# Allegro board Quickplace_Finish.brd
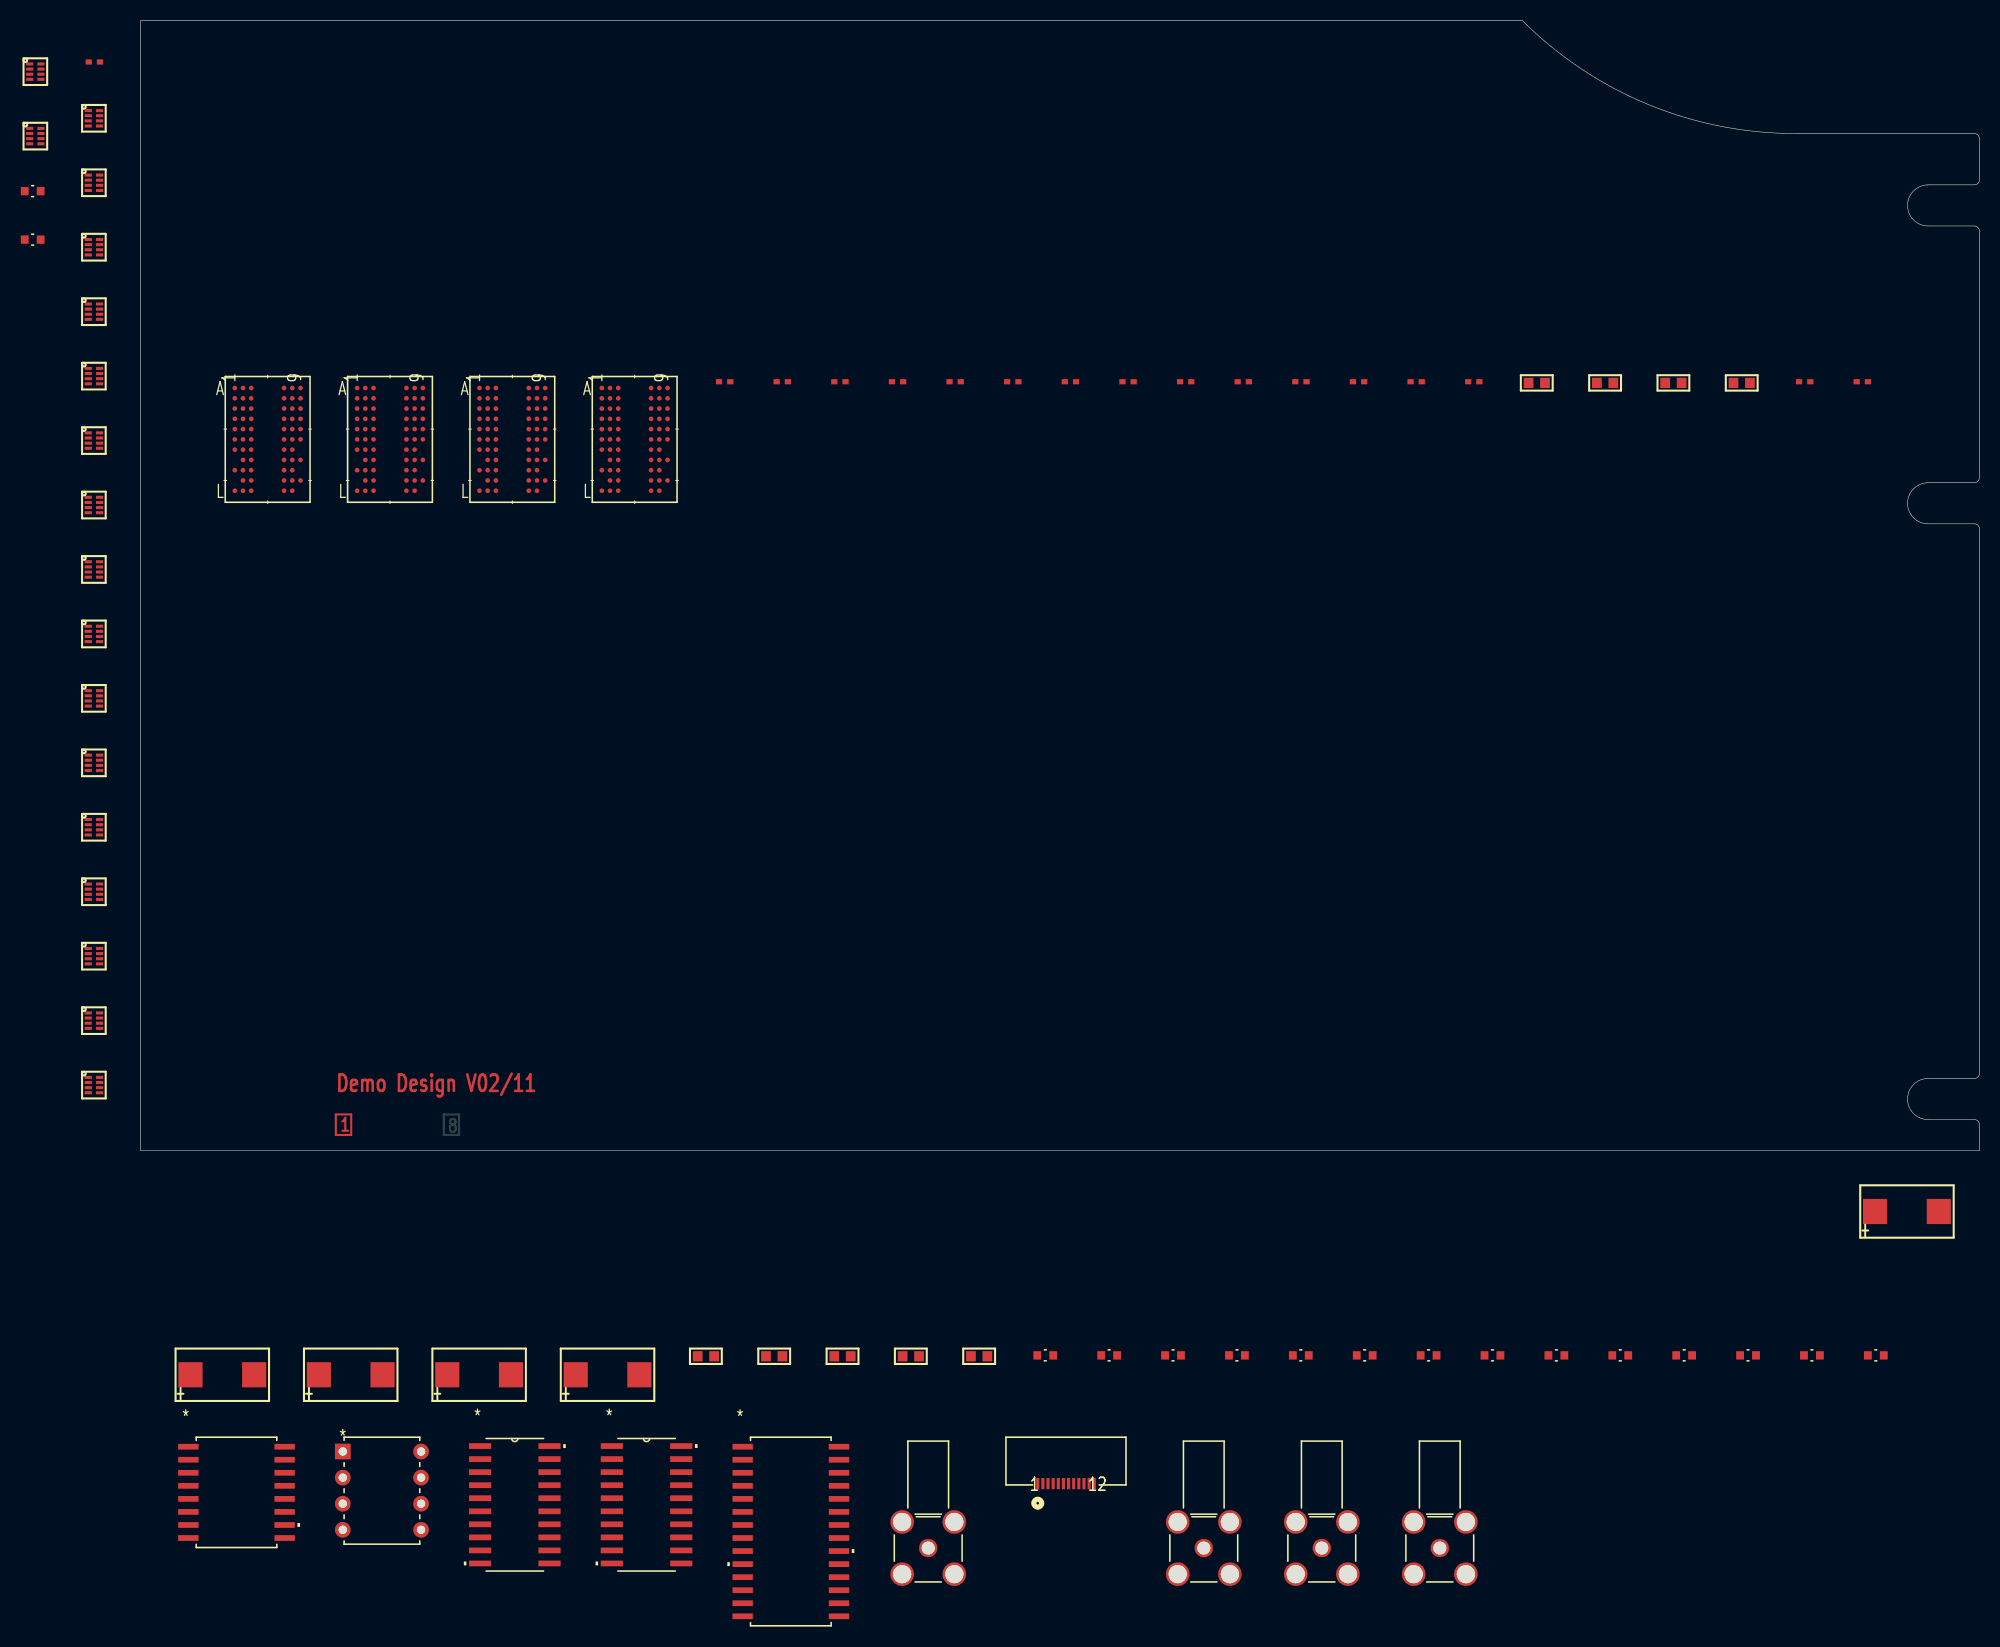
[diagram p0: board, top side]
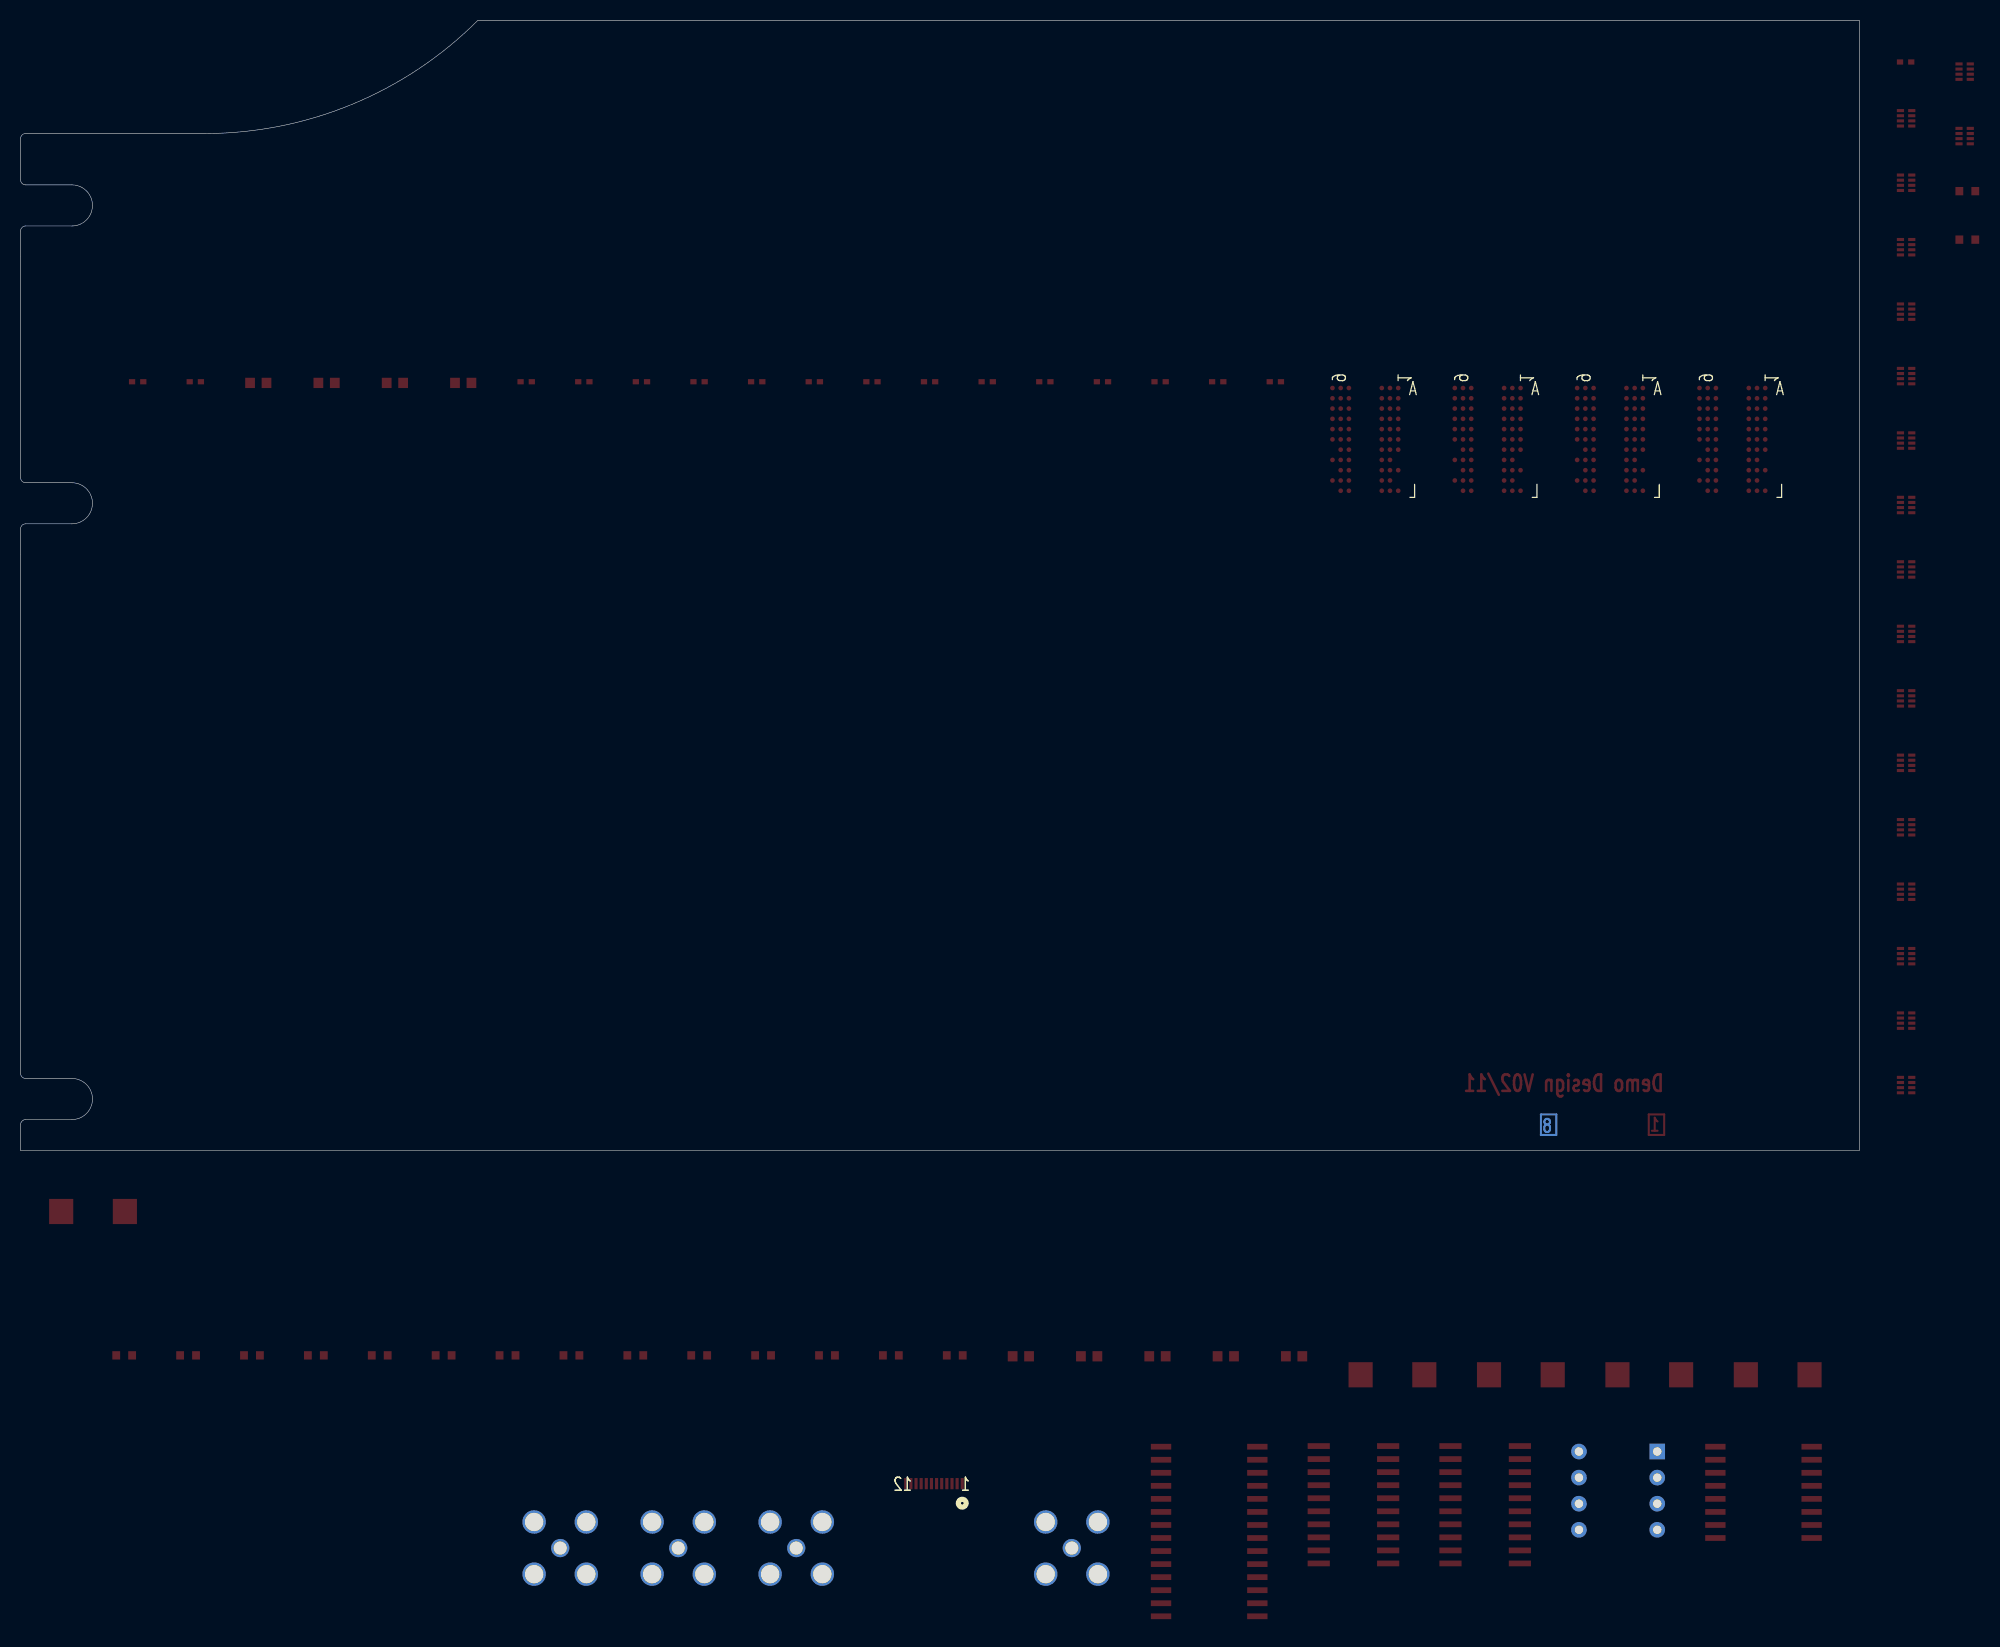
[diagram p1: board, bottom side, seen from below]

Outline 179 x 110 mm; copper layers: TOP, GND1, I1, POW1, GND2, I2, POW2, BOTTOM. Coordinates in mm from the lower left corner of the outline.
Outline path: 0,110 134.5,110 arc(146.68,101.86) 161.06,99 178.5,99 arc(178.85,98.85) 179,98.5 179,94.5 arc(178.85,94.15) 178.5,94 174,94 arc(172.59,93.41) 172,92 arc(172.59,90.59) 174,90 178.5,90 arc(178.85,89.85) 179,89.5 179,65.5 arc(178.85,65.15) 178.5,65 174,65 arc(172.59,64.41) 172,63 arc(172.59,61.59) 174,61 178.5,61 arc(178.85,60.85) 179,60.5 179,7.5 arc(178.85,7.15) 178.5,7 174,7 arc(172.59,6.41) 172,5 arc(172.59,3.59) 174,3 178.5,3 arc(178.85,2.85) 179,2.5 179,0 0,0 0,110

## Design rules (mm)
constraint set DEFAULT: min track width 0.12
net group 220V: nets 220VIN N9903369
net group D+: nets D+ N64620
net group D-: nets D- N64584
net group DDR2_DQS0: nets DDR2_M.MDQS0 DDR2_M.MDQS#0
net group DDR2_DQS1: nets DDR2.DQS1 DDR2.DQS#1
net group DDR2_DQS2: nets DDR2_M.MDQS2 DDR2_M.MDQS#2
net group DDR2_DQS3: nets DDR2.DQS3 DDR2.DQS#3
net group DDR3.DQ1: nets DDR3.DQ1 DDR3_M.MDQ1
net group DDR3.DQ2: nets DDR3.DQ2 DDR3_M.MDQ2
net group DDR3.DQS0: nets DDR3.DQS0 DDR3_M.MDQS0
net group DDR3.DQS#0: nets DDR3.DQS#0 DDR3_M.MDQS#0
net group DP_DDR2.DQS#0: nets DDR2.DQS0 DDR2.DQS#0
net group DP_DDR2.DQS#2: nets DDR2.DQS2 DDR2.DQS#2
net group L: nets N9927430 N9927434
net group LVDS_CLKN1: nets LVDS_CLKN1 N11185
net group LVDS_CLKP1: nets LVDS_CLKP1 N09783
net group N04579: nets N04579 N05028
net group N06416: nets N06416 N06432
net group N07590: nets N07590 N07606
net group N08030: nets N08030 N08046
net group N14938: nets N04399 N14938
net group N14942: nets N04484 N14942
net group N15446: nets N04241 N15446
net group N15450: nets N04318 N15450
net group PCIE.PERN0: nets N56952 PCIE.PERN0
net group PCIE.PERN1: nets N56956 PCIE.PERN1
net group PCIE.PERN2: nets N56950 PCIE.PERN2
net group PCIE.PERN3: nets N56954 PCIE.PERN3
net group PCIE.PERP0: nets N57097 PCIE.PERP0
net group PCIE.PERP1: nets N57240 PCIE.PERP1
net group PCIE.PERP2: nets N57385 PCIE.PERP2
net group PCIE.PERP3: nets N57532 PCIE.PERP3
net group PCIE.PETN0: nets N58134 PCIE.PETN0
net group PCIE.PETN1: nets N58138 PCIE.PETN1
net group PCIE.PETN2: nets N58142 PCIE.PETN2
net group PCIE.PETN3: nets N58146 PCIE.PETN3
net group PCIE.PETP0: nets N58154 PCIE.PETP0
net group PCIE.PETP1: nets N58162 PCIE.PETP1
net group PCIE.PETP2: nets N58150 PCIE.PETP2
net group PCIE.PETP3: nets N58158 PCIE.PETP3
net group PCIE.REFCLK+: nets N06722 PCIE.REFCLK+
net group PCIE.REFCLK-: nets N06858 PCIE.REFCLK-
net group STDA_SSRX+: nets N64724 STDA_SSRX+
net group STDA_SSRX-: nets N64696 STDA_SSRX-
net group STDA_SSTX+: nets N64864 STDA_SSTX+
net group STDA_SSTX-: nets N64816 STDA_SSTX-
net group AD_DA: nets AD_CS AD_DB0 AD_DB1 AD_DB2 AD_DB3 AD_DB4 AD_DB5 AD_DB6 AD_DB7 AD_DB8 AD_DB9 AD_DB10 AD_DB11 AD_DB12 AD_DB13 AD_FL0 AD_FL1 AD_IRQ2 AD_RD N00752 N00770 N00798 N00829 N00863 N00900 N01007 N01138 N01306 N01356 N01440 N01527 N01617 N01710 N04350 N06404 N07578 N08018
net group DDR2.A0: nets DDR2.A0
net group DDR2.A1: nets DDR2.A1
net group DDR2.A2: nets DDR2.A2
net group DDR2.A3: nets DDR2.A3
net group DDR2.A4: nets DDR2.A4
net group DDR2.A5: nets DDR2.A5
net group DDR2.A6: nets DDR2.A6
net group DDR2.A7: nets DDR2.A7
net group DDR2.A8: nets DDR2.A8
net group DDR2.A9: nets DDR2.A9
net group DDR2.A10: nets DDR2.A10
net group DDR2.A11: nets DDR2.A11
net group DDR2.A12: nets DDR2.A12
net group DDR2.A13: nets DDR2.A13
net group DDR2.BA0: nets DDR2.BA0
net group DDR2.BA1: nets DDR2.BA1
net group DDR2.CAS: nets DDR2.CAS
net group DDR2.ODT0: nets DDR2.ODT0
net group DDR2.RAS: nets DDR2.RAS
net group DDR2.S0: nets DDR2.S0
net group DDR2.WE: nets DDR2.WE
net group DDR2[0..71]: nets DDR2.CK1 DDR2.CK#1 DDR2_M.MDQS1 DDR2_M.MDQS3
net group DDR2_A_EL: nets DDR2_M.MA0 DDR2_M.MA1 DDR2_M.MA2 DDR2_M.MA3 DDR2_M.MA4 DDR2_M.MA5 DDR2_M.MA6 DDR2_M.MA7 DDR2_M.MA8 DDR2_M.MA9 DDR2_M.MA10 DDR2_M.MA11 DDR2_M.MA12 DDR2_M.MA13 DDR2_M.MBA0 DDR2_M.MBA1 DDR2_M.MCAS DDR2_M.MODT0 DDR2_M.MRAS DDR2_M.MS0 DDR2_M.MWE
net group DDR2_D0_EL: nets DDR2.DM0 DDR2.DQ0 DDR2.DQ1 DDR2.DQ2 DDR2.DQ3 DDR2.DQ4 DDR2.DQ5 DDR2.DQ6 DDR2.DQ7 DDR2.RDQS#0 DDR2_M.MDM0 DDR2_M.MDQ0 DDR2_M.MDQ1 DDR2_M.MDQ2 DDR2_M.MDQ3 DDR2_M.MDQ4 DDR2_M.MDQ5 DDR2_M.MDQ6 DDR2_M.MDQ7 DDR2_M.MRDQS#0
net group DDR2_D1_EL: nets DDR2.DM1 DDR2.DQ8 DDR2.DQ9 DDR2.DQ10 DDR2.DQ11 DDR2.DQ12 DDR2.DQ13 DDR2.DQ14 DDR2.DQ15 DDR2.RDQS#1 DDR2_M.MDM1 DDR2_M.MDQ8 DDR2_M.MDQ9 DDR2_M.MDQ10 DDR2_M.MDQ11 DDR2_M.MDQ12 DDR2_M.MDQ13 DDR2_M.MDQ14 DDR2_M.MDQ15 DDR2_M.MDQS#1 DDR2_M.MRDQS#1
net group DDR2_D2_EL: nets DDR2.DM2 DDR2.DQ16 DDR2.DQ17 DDR2.DQ18 DDR2.DQ19 DDR2.DQ20 DDR2.DQ21 DDR2.DQ22 DDR2.DQ23 DDR2.RDQS#2 DDR2_M.MDM2 DDR2_M.MDQ16 DDR2_M.MDQ17 DDR2_M.MDQ18 DDR2_M.MDQ19 DDR2_M.MDQ20 DDR2_M.MDQ21 DDR2_M.MDQ22 DDR2_M.MDQ23 DDR2_M.MRDQS#2
net group DDR2_D3_EL: nets DDR2.DM3 DDR2.DQ24 DDR2.DQ25 DDR2.DQ26 DDR2.DQ27 DDR2.DQ28 DDR2.DQ29 DDR2.DQ30 DDR2.DQ31 DDR2.RDQS#3 DDR2_M.MDM3 DDR2_M.MDQ24 DDR2_M.MDQ25 DDR2_M.MDQ26 DDR2_M.MDQ27 DDR2_M.MDQ28 DDR2_M.MDQ29 DDR2_M.MDQ30 DDR2_M.MDQ31 DDR2_M.MDQS#3 DDR2_M.MRDQS#3
net group DDR2_M.MCKE0: nets DDR2.CKE0
net group DDR3.DQ0: nets DDR3.DQ0
net group DDR3.DQ3: nets DDR3.DQ3
net group DDR3.DQ4: nets DDR3.DQ4
net group DDR3.DQ5: nets DDR3.DQ5
net group DDR3.DQ6: nets DDR3.DQ6
net group DDR3.DQ7: nets DDR3.DQ7
net group DDR3.DQ8: nets DDR3.DQ8
net group DDR3.DQ9: nets DDR3.DQ9
net group DDR3.DQ10: nets DDR3.DQ10
net group DDR3.DQ11: nets DDR3.DQ11
net group DDR3.DQ12: nets DDR3.DQ12
net group DDR3.DQ13: nets DDR3.DQ13
net group DDR3.DQ14: nets DDR3.DQ14
net group DDR3.DQ15: nets DDR3.DQ15
net group DDR3.DQS1: nets DDR3.DQS1
net group DDR3.DQS2: nets DDR3.DQS2
net group DDR3.DQS3: nets DDR3.DQS3
net group DDR3.DQS#1: nets DDR3.DQS#1
net group DDR3.DQS#2: nets DDR3.DQS#2
net group DDR3.DQS#3: nets DDR3.DQS#3
net group DDR3[0..54]: nets DDR3.A0 DDR3.A1 DDR3.A2 DDR3.A3 DDR3.A4 DDR3.A5 DDR3.A6 DDR3.A7 DDR3.A8 DDR3.A9 DDR3.A10 DDR3.A11 DDR3.A12 DDR3.A13 DDR3.A14 DDR3.BA0 DDR3.BA1 DDR3.BA2 DDR3.CAS DDR3.CK1 DDR3.CK#1 DDR3.CKE0 DDR3.ODT0 DDR3.RAS DDR3.RESET DDR3.S0 DDR3.WE
net group DDR3_M.MDM0: nets DDR3.DM0
net group DDR3_M.MDM1: nets DDR3.DM1
net group DDR3_M.MDM2: nets DDR3.DM2
net group DDR3_M.MDM3: nets DDR3.DM3
net group DDR3_SINGLE: nets N6521820 N6522732 N6522947 N6523197 N6859922
net group LOGIC: nets N01473 N01729 PGOOD_1.5V PGOOD_1.8V
net group MISC: nets 0.9VREF 0.75VREF 0VIN 1.2V 3.3V FB GATE N00305 N01108 N01139 N01192 N01323 N01619 N03618 N03634 N20586 N20602 N20606 N20610 N20650 N20774 N633172 N633472 N633476 N633480 N633520 N633648 N9903199 N9903225 N9903279 N9903519 N9908752 PE SENSE SHIELD1 SHIELD2 SKIP VCC VINT
net group N: nets N9927466
net group PCI_SINGLE: nets TDIO
net group PCIE[0..23]: nets PCIE.PERST# PCIE.PRSNT#1 PCIE.PRSNT#2 PCIE.SMCLK PCIE.SMDAT PCIE.WAKE#
net group POWER: nets 0.75VTT 1.0V 1.5V 1.8V 2.5V 2.5VREF 5V 12V +15V -15V AGND DGND GND_IN N00359 N00418 N00468 N04407 N04552 N20590 N20594 N20598 N20626 N20798 N20810 N633192 N633212 N633232 N633496 N633672 N633684
net group POWER_IN: nets DRAIN
net group VID: nets VID_D0 VID_D1 VID_D2 VID_D3 VID_D4 VID_FST VID_QCLK VID_SCL

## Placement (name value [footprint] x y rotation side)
C100  10u  [CAPP_TAJ_D]  171.94 -5.95 0 top
C101  10u  [CAPP_TAJ_D]  7.95 -21.85 0 top
C102  100n  [CAP_0603]  55.02 -20.05 0 top
C103  100n  [CAP_0603]  61.67 -20.05 0 top
C104  100n  [CAP_0603]  68.33 -20.05 0 top
C105  10u  [CAPP_TAJ_D]  20.45 -21.85 0 top
C106  100n  [CAP_0603]  74.97 -20.05 0 top
C107  10u  [CAPP_TAJ_D]  32.95 -21.85 0 top
C108  10u  [CAPP_TAJ_D]  45.45 -21.85 0 top
C109  100n  [CAP_0603]  81.62 -20.05 0 top
C504  100n  [CAP_0402]  167.6 74.84 0 top
C505  100n  [CAP_0402]  161.99 74.84 0 top
C506  2.2u  [CAP_0603]  135.91 74.72 0 top
C507  100n  [CAP_0402]  129.78 74.84 0 top
C508  100n  [CAP_0402]  56.85 74.84 0 top
C509  2.2u  [CAP_0603]  142.56 74.72 0 top
C510  100n  [CAP_0402]  62.46 74.84 0 top
C511  100n  [CAP_0402]  73.68 74.84 0 top
C512  2.2u  [CAP_0603]  149.21 74.72 0 top
C513  100n  [CAP_0402]  68.07 74.84 0 top
C514  100n  [CAP_0402]  84.9 74.84 0 top
C515  2.2u  [CAP_0603]  155.86 74.72 0 top
C516  100n  [CAP_0402]  79.29 74.84 0 top
C517  100n  [CAP_0402]  107.34 74.84 0 top
C518  100n  [CAP_0402]  90.51 74.84 0 top
C519  100n  [CAP_0402]  96.12 74.84 0 top
C520  100n  [CAP_0402]  101.73 74.84 0 top
C521  100n  [CAP_0402]  124.17 74.84 0 top
C522  100n  [CAP_0402]  112.95 74.84 0 top
C523  100n  [CAP_0402]  118.56 74.84 0 top
C524  22p  [CAP_0402]  -4.5 105.97 0 top
NOREF  -  []  0 0 0 top
NOREF#2  -  []  3.11 5.64 0 top
NOREF#3  -  []  0 0 0 top
NOREF#4  -  []  13 5 90 top
NOREF#5  -  []  0 0 0 top
NOREF#6  -  []  179 0 90 top
NOREF#7  -  []  0 0 90 top
NOREF#8  -  []  -50.46 -133.7 0 top
NOREF#9  -  []  213.2 115.2 0 top
NOREF#10  -  []  134.5 110 0 top
NOREF#11  -  []  15.87 7.79 0 top
NOREF#12  -  []  0 0 0 top
NOREF#13  -  []  178.5 99 90 top
NOREF#14  -  []  179 0 90 top
NOREF#15  -  []  179 0 90 top
NOREF#16  -  []  178.88 7.17 90 top
NOREF#17  -  []  172 5 90 top
NOREF#18  -  []  0 0 90 top
R100  1k  [RES_0603]  88.06 -19.96 0 top
R101  1k  [RES_0603]  94.28 -19.96 0 top
R102  1k  [RES_0603]  100.5 -19.96 0 top
R103  1k  [RES_0603]  106.72 -19.96 0 top
R104  1k  [RES_0603]  112.94 -19.96 0 top
R105  1k  [RES_0603]  119.16 -19.96 0 top
R106  1k  [RES_0603]  125.38 -19.96 0 top
R107  1k  [RES_0603]  131.6 -19.96 0 top
R108  9.1k  [RES_0603]  137.81 -19.96 0 top
R109  9.1k  [RES_0603]  144.03 -19.96 0 top
R110  9.1k  [RES_0603]  150.25 -19.96 0 top
R111  9.1k  [RES_0603]  156.47 -19.96 0 top
R112  1.2k  [RES_0603]  162.69 -19.96 0 top
R113  1.2k  [RES_0603]  168.91 -19.96 0 top
R500  22  [RES_RS4N]  -4.55 100.48 0 top
R501  22  [RES_RS4N]  -4.55 94.21 0 top
R502  22  [RES_RS4N]  -4.55 87.93 0 top
R503  22  [RES_RS4N]  -4.55 81.66 0 top
R504  7.5R  [RES_RS4N]  -4.55 25.18 0 top
R505  7.5R  [RES_RS4N]  -4.55 18.91 0 top
R506  200  [RES_0603]  -10.51 93.39 0 top
R507  7.5R  [RES_RS4N]  -4.55 12.63 0 top
R508  7.5R  [RES_RS4N]  -4.55 6.36 0 top
R509  7.5R  [RES_RS4N]  -10.25 105.03 0 top
R510  7.5R  [RES_RS4N]  -10.25 98.75 0 top
R511  200  [RES_0603]  -10.51 88.67 0 top
R512  22  [RES_RS4N]  -4.55 75.38 0 top
R513  22  [RES_RS4N]  -4.55 69.11 0 top
R514  22  [RES_RS4N]  -4.55 62.83 0 top
R515  22  [RES_RS4N]  -4.55 56.56 0 top
R516  22  [RES_RS4N]  -4.55 50.28 0 top
R517  22  [RES_RS4N]  -4.55 44.01 0 top
R518  22  [RES_RS4N]  -4.55 37.73 0 top
R519  22  [RES_RS4N]  -4.55 31.46 0 top
U100  AD713  [SO16_1_27X9_30]  9.33 -33.3 0 top
U101  AD780  [SO8_1_27X4_90]  19.68 -29.32 0 top
U102  74AHC245  [SO20_1_27X9_30]  36.43 -34.5 0 top
U103  74AHC245  [SO20_1_27X9_30]  49.25 -34.5 0 top
U104  AD7862  [SO28_1_27X9_30]  63.29 -37.11 0 top
U504  MT47H64M8CF-25EG  [FBGA60_8X10_MRN]  48.09 69.22 0 top
U505  MT47H64M8CF-25EG  [FBGA60_8X10_MRN]  24.27 69.22 0 top
U506  MT47H64M8CF-25EG  [FBGA60_8X10_MRN]  36.18 69.22 0 top
U507  MT47H64M8CF-25EG  [FBGA60_8X10_MRN]  12.36 69.22 0 top
X100  FPC12  [ZIF12_FLEX]  87.33 -32.45 0 top
X101  SMB  [SMB_90]  103.49 -38.72 0 top
X102  SMB  [SMB_90]  76.67 -38.72 0 top
X103  SMB  [SMB_90]  114.98 -38.72 0 top
X104  SMB  [SMB_90]  126.47 -38.72 0 top

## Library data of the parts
C100 C101 C105 C107 C108 = CAPPOL_T: User Part Number: FC-CAP-0049; alternate symbols: ((capp_taj_d_gd)); room: Analog_In; signal model: DEFAULT_CAPACITOR_1e+07pF_1_2
C102-C104 C106 C109 = CAP_V: User Part Number: FC-CAP-0037; alternate symbols: ((cap_0603_gd)); room: Analog_In; signal model: DEFAULT_CAPACITOR_100000pF_2_1
C504 C505 C507 C508 C510 C511 C513 C514 C516-C523 = CAP_V: User Part Number: FC-CAP-0099; Tolerance: TOL; signal model: DEFAULT_CAPACITOR_100000pF_2_1; room: DDR2
C506 C509 C512 C515 = CAP_V: User Part Number: FC-CAP-0100; alternate symbols: ((cap_0603_gd)); signal model: DEFAULT_CAPACITOR_2.2e+06pF_2_1; room: DDR2
C524 = CAP_H: User Part Number: FC-CAP-0080; Tolerance: TOL; signal model: DEFAULT_CAPACITOR_22pF_2_1; room: DDR2
R100-R107 = RES_V: User Part Number: FC-RES-0077; Tolerance: TOL; alternate symbols: ((res_0603_gd)); room: Analog_In; signal model: DEFAULT_RESISTOR_1000OHM_2_1
R108-R111 = RES_H: User Part Number: FC-RES-0100; Tolerance: TOL; alternate symbols: ((res_0603_gd)); room: Analog_In; signal model: DEFAULT_RESISTOR_9100OHM_2_1
R112 R113 = RES_V: User Part Number: FC-RES-0079; Tolerance: TOL; alternate symbols: ((res_0603_gd)); room: Analog_In; signal model: DEFAULT_RESISTOR_1200OHM_2_1
R500-R503 R512-R519 = RES_H_4x: User Part Number: FC-RAR-0225; alternate symbols: ((res_rs4n_gd)); signal model: rpack_x4_22r; room: DDR2
R504 R505 R507-R510 = RES_H_4x: User Part Number: FC-RAR-0282; alternate symbols: ((res_rs4n_gd)); signal model: rpack_x4_7.5R; room: DDR2
R506 R511 = RES_V: User Part Number: FC-RES-0060; Tolerance: TOL; alternate symbols: ((res_0603_gd)); signal model: DEFAULT_RESISTOR_200OHM_2_1; room: DDR2
U100 = AD713_SO: User Part Number: FC-IC-0023; Tolerance: TOL; room: Analog_In
U101 = IC_AD780_2: User Part Number: FC-IC-0024; Tolerance: TOL; room: Analog_In
U102 U103 = 74LS245: User Part Number: FC-IC-0927; Tolerance: TOL; room: Analog_In
U104 = IC_AD7862: User Part Number: FC-IC-0022; Tolerance: TOL; room: Analog_In
U504-U507 = MT47H64M8CF-25EG: User Part Number: PN; Tolerance: TOL
X100 = CON_12: User Part Number: FC-CON-0010; Tolerance: TOL
X101-X104 = CON_SMB: User Part Number: FC-CON-0002; Tolerance: TOL; alternate symbols: ((smb_90))

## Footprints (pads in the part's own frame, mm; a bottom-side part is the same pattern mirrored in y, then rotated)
CAP_0402
  rect 0.61x0.508 smd: 1(-0.546,0) 2(0.546,0)
CAP_0603
  rect 0.95x1 smd: 1(-0.8,0) 2(0.8,0)
CAPP_TAJ_D
  rect 2.35x2.45 smd: 1(-3.1,0) 2(3.1,0)
FBGA60_8X10_MRN
  round 0.457 smd: A1(-3.2,5) A2(-2.4,5) A3(-1.6,5) A7(1.6,5) A8(2.4,5) A9(3.2,5) B1(-3.2,4) B2(-2.4,4) B3(-1.6,4) B7(1.6,4) B8(2.4,4) B9(3.2,4) C1(-3.2,3) C2(-2.4,3) C3(-1.6,3) C7(1.6,3) C8(2.4,3) C9(3.2,3) D1(-3.2,2) D2(-2.4,2) D3(-1.6,2) D7(1.6,2) D8(2.4,2) D9(3.2,2) E1(-3.2,1) E2(-2.4,1) E3(-1.6,1) E7(1.6,1) E8(2.4,1) E9(3.2,1) F1(-3.2,0) F2(-2.4,0) F3(-1.6,0) F7(1.6,0) F8(2.4,0) F9(3.2,0) G1(-3.2,-1) G2(-2.4,-1) G3(-1.6,-1) G7(1.6,-1) G8(2.4,-1) H2(-2.4,-2) H3(-1.6,-2) H7(1.6,-2) H8(2.4,-2) H9(3.2,-2) J1(-3.2,-3) J2(-2.4,-3) J3(-1.6,-3) J7(1.6,-3) J8(2.4,-3) K2(-2.4,-4) K3(-1.6,-4) K7(1.6,-4) K8(2.4,-4) K9(3.2,-4) L1(-3.2,-5) L2(-2.4,-5) L3(-1.6,-5) L7(1.6,-5) L8(2.4,-5)
RES_0603
  rect 0.762x0.813 smd: 1(-0.775,0) 2(0.775,0)
RES_RS4N
  rect 0.7x0.3 smd: 1(-0.55,0.75) 2(-0.55,0.25) 3(-0.55,-0.25) 4(-0.55,-0.75) 5(0.55,-0.75) 6(0.55,-0.25) 7(0.55,0.25) 8(0.55,0.75)
SMB_90
  round 1.778 hole 1.27: 1(0,0)
  round 2.286 hole 1.778: 2(-2.54,2.54) 3(-2.54,-2.54) 4(2.54,-2.54) 5(2.54,2.54)
SO8_1_27X4_90
  rect 1.524x1.524 hole 0.813: 1(0,0)
  round 1.524 hole 0.813: 2(0,-2.54) 3(0,-5.08) 4(0,-7.62) 5(7.62,-7.62) 6(7.62,-5.08) 7(7.62,-2.54) 8(7.62,0)
SO16_1_27X9_30
  rect 1.981x0.559 smd: 1(-4.686,4.445) 2(-4.686,3.175) 3(-4.686,1.905) 4(-4.686,0.635) 5(-4.686,-0.635) 6(-4.686,-1.905) 7(-4.686,-3.175) 8(-4.686,-4.445) 9(4.686,-4.445) 10(4.686,-3.175) 11(4.686,-1.905) 12(4.686,-0.635) 13(4.686,0.635) 14(4.686,1.905) 15(4.686,3.175) 16(4.686,4.445)
SO20_1_27X9_30
  rect 2.159x0.559 smd: 1(-3.378,5.715) 2(-3.378,4.445) 3(-3.378,3.175) 4(-3.378,1.905) 5(-3.378,0.635) 6(-3.378,-0.635) 7(-3.378,-1.905) 8(-3.378,-3.175) 9(-3.378,-4.445) 10(-3.378,-5.715) 11(3.378,-5.715) 12(3.378,-4.445) 13(3.378,-3.175) 14(3.378,-1.905) 15(3.378,-0.635) 16(3.378,0.635) 17(3.378,1.905) 18(3.378,3.175) 19(3.378,4.445) 20(3.378,5.715)
SO28_1_27X9_30
  rect 1.981x0.559 smd: 1(-4.686,8.255) 2(-4.686,6.985) 3(-4.686,5.715) 4(-4.686,4.445) 5(-4.686,3.175) 6(-4.686,1.905) 7(-4.686,0.635) 8(-4.686,-0.635) 9(-4.686,-1.905) 10(-4.686,-3.175) 11(-4.686,-4.445) 12(-4.686,-5.715) 13(-4.686,-6.985) 14(-4.686,-8.255) 15(4.686,-8.255) 16(4.686,-6.985) 17(4.686,-5.715) 18(4.686,-4.445) 19(4.686,-3.175) 20(4.686,-1.905) 21(4.686,-0.635) 22(4.686,0.635) 23(4.686,1.905) 24(4.686,3.175) 25(4.686,4.445) 26(4.686,5.715) 27(4.686,6.985) 28(4.686,8.255)
ZIF12_FLEX
  rect 0.305x1.092 smd: 1(0,0) 2(0.5,0) 3(1,0) 4(1.5,0) 5(2,0) 6(2.5,0) 7(3,0) 8(3.5,0) 9(4,0) 10(4.5,0) 11(5,0) 12(5.5,0)

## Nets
1.8V: C504.2(B) C505.2(B) C506.2(B) C507.2(B) C508.2(B) C509.2(B) C510.2(B) C511.2(B) C512.2(B) C513.2(B) C514.2(B) C515.2(B) C516.2(B) C517.2(B) C518.2(B) C519.2(B) C520.2(B) C521.2(B) C522.2(B) C523.2(B)
2.5VREF: C107.1(P) U101.6(VOUT) U104.19(VREF)
3.3V: X100.2
5V: C104.2(B) C105.1(P) C106.2(B) C108.1(P) C109.2(B) R112.2(B) R113.2(B) U101.2 U102.1 U102.20(VCC) U103.1 U103.20(VCC) U104.24
+15V: C100.1(P) C102.2(B) U100.4
-15V: C101.2 C103.1 U100.13(V-)
AGND: C100.2 C101.1(P) C102.1 C103.2(B) C104.1 C107.2 C108.2 C109.1 R100.1 R101.1 R102.1 R103.1 R104.1 R105.1 R106.1 R107.1 U101.4 U104.16 U104.27 X101.2 X101.3 X101.4 X101.5(B3) X102.2 X102.3 X102.4 X102.5(B3) X103.2 X103.3 X103.4 X103.5(B3) X104.2 X104.3 X104.4 X104.5(B3)
DGND: C105.2 C106.1 C504.1 C505.1 C506.1 C507.1 C508.1 C509.1 C510.1 C511.1 C512.1 C513.1 C514.1 C515.1 C516.1 C517.1 C518.1 C519.1 C520.1 C521.1 C522.1 C523.1 U102.10 U103.8 U103.9 U103.10 U104.7 X100.1 X100.12
VDD: U504.A1 U505.A1 U506.A1 U507.A1
VDD_1: U504.E9 U505.E9 U506.E9 U507.E9
VDD_2: U504.H9 U505.H9 U506.H9 U507.H9
VDD_3: U504.L1 U505.L1 U506.L1 U507.L1
VDDL: U504.E1 U505.E1 U506.E1 U507.E1
VDDQ: U504.A9 U505.A9 U506.A9 U507.A9
VDDQ_1: U504.C1 U505.C1 U506.C1 U507.C1
VDDQ_2: U504.C3 U505.C3 U506.C3 U507.C3
VDDQ_3: U504.C7 U505.C7 U506.C7 U507.C7
VDDQ_4: U504.C9 U505.C9 U506.C9 U507.C9
VSS: U504.A3 U505.A3 U506.A3 U507.A3
VSS_1: U504.E3 U505.E3 U506.E3 U507.E3
VSS_2: U504.J1 U505.J1 U506.J1 U507.J1
VSS_3: U504.K9(VSS_3) U505.K9(VSS_3) U506.K9(VSS_3) U507.K9(VSS_3)
VSSDL: U504.E7 U505.E7 U506.E7 U507.E7
VSSQ: U504.A7 U505.A7 U506.A7 U507.A7
VSSQ_1: U504.B2 U505.B2 U506.B2 U507.B2
VSSQ_2: U504.B8 U505.B8 U506.B8 U507.B8
VSSQ_3: U504.D2 U505.D2 U506.D2 U507.D2
VSSQ_4: U504.D8 U505.D8 U506.D8 U507.D8
AD_CS: R112.1 U102.19 U103.19 U104.21
AD_DB0: U102.18
AD_DB1: U102.17
AD_DB2: U102.16
AD_DB3: U102.15
AD_DB4: U102.14
AD_DB5: U102.13
AD_DB6: U102.12
AD_DB7: U102.11
AD_DB8: U103.18
AD_DB9: U103.17
AD_DB10: U103.16
AD_DB11: U103.15
AD_DB12: U103.14
AD_DB13: U103.13
AD_FL0: U104.8
AD_FL1: U104.20
AD_IRQ2: U104.23
AD_RD: R113.1 U104.22
DDR2.A0: R505.4
DDR2.A1: R508.2
DDR2.A2: R507.1
DDR2.A3: R509.2
DDR2.A4: R504.2
DDR2.A5: R508.3
DDR2.A6: R504.1
DDR2.A7: R510.1
DDR2.A8: R504.4
DDR2.A9: R509.1
DDR2.A10: R509.4
DDR2.A11: R508.1
DDR2.A12: R509.3
DDR2.A13: R507.2
DDR2.BA0: R508.4
DDR2.BA1: R507.4
DDR2.CAS: R504.3
DDR2.CK1: R506.2(B) R511.2(B)
DDR2.CK#1: R506.1 R511.1
DDR2.CKE0: C524.1
DDR2.DM0: R503.4
DDR2.DM1: R519.2
DDR2.DM2: R519.4
DDR2.DM3: R517.1
DDR2.DQ0: R503.3
DDR2.DQ1: R513.3
DDR2.DQ2: R512.2
DDR2.DQ3: R513.4
DDR2.DQ4: R503.1
DDR2.DQ5: R512.1
DDR2.DQ6: R513.2
DDR2.DQ7: R512.4
DDR2.DQ8: R517.4
DDR2.DQ9: R518.3
DDR2.DQ10: R517.3
DDR2.DQ11: R519.3
DDR2.DQ12: R502.1
DDR2.DQ13: R515.2
DDR2.DQ14: R502.2
DDR2.DQ15: R515.1
DDR2.DQ16: R516.1
DDR2.DQ17: R518.4
DDR2.DQ18: R512.3
DDR2.DQ19: R500.3
DDR2.DQ20: R502.4
DDR2.DQ21: R516.3
DDR2.DQ22: R518.2
DDR2.DQ23: R518.1
DDR2.DQ24: R515.3
DDR2.DQ25: R502.3
DDR2.DQ26: R519.1
DDR2.DQ27: R500.4
DDR2.DQ28: R516.4
DDR2.DQ29: R515.4
DDR2.DQ30: R500.2
DDR2.DQ31: R517.2
DDR2.DQS0: R501.1
DDR2.DQS1: R514.3
DDR2.DQS2: R501.4
DDR2.DQS3: R514.2
DDR2.DQS#0: R501.2
DDR2.DQS#1: R514.4
DDR2.DQS#2: R501.3
DDR2.DQS#3: R514.1
DDR2.ODT0: R505.1
DDR2.RAS: R505.3
DDR2.RDQS#0: R513.1
DDR2.RDQS#1: R500.1
DDR2.RDQS#2: R503.2
DDR2.RDQS#3: R516.2
DDR2.S0: R505.2
DDR2.WE: R507.3
DDR2_M.MA0: R505.5(B)
DDR2_M.MA1: R508.7
DDR2_M.MA2: R507.8
DDR2_M.MA3: R509.7
DDR2_M.MA4: R504.7
DDR2_M.MA5: R508.6
DDR2_M.MA6: R504.8
DDR2_M.MA7: R510.8
DDR2_M.MA8: R504.5(B)
DDR2_M.MA9: R509.8
DDR2_M.MA10: R509.5(B)
DDR2_M.MA11: R508.8
DDR2_M.MA12: R509.6
DDR2_M.MA13: R507.7
DDR2_M.MBA0: R508.5(B)
DDR2_M.MBA1: R507.5(B)
DDR2_M.MCAS: R504.6
DDR2_M.MCKE0: C524.2(B)
DDR2_M.MDM0: R503.5(B)
DDR2_M.MDM1: R519.7
DDR2_M.MDM2: R519.5(B)
DDR2_M.MDM3: R517.8
DDR2_M.MDQ0: R503.6
DDR2_M.MDQ1: R513.6
DDR2_M.MDQ2: R512.7
DDR2_M.MDQ3: R513.5(B)
DDR2_M.MDQ4: R503.8
DDR2_M.MDQ5: R512.8
DDR2_M.MDQ6: R513.7
DDR2_M.MDQ7: R512.5(B)
DDR2_M.MDQ8: R517.5(B)
DDR2_M.MDQ9: R518.6
DDR2_M.MDQ10: R517.6
DDR2_M.MDQ11: R519.6
DDR2_M.MDQ12: R502.8
DDR2_M.MDQ13: R515.7
DDR2_M.MDQ14: R502.7
DDR2_M.MDQ15: R515.8
DDR2_M.MDQ16: R516.8
DDR2_M.MDQ17: R518.5(B)
DDR2_M.MDQ18: R512.6
DDR2_M.MDQ19: R500.6
DDR2_M.MDQ20: R502.5(B)
DDR2_M.MDQ21: R516.6
DDR2_M.MDQ22: R518.7
DDR2_M.MDQ23: R518.8
DDR2_M.MDQ24: R515.6
DDR2_M.MDQ25: R502.6
DDR2_M.MDQ26: R519.8
DDR2_M.MDQ27: R500.5(B)
DDR2_M.MDQ28: R516.5(B)
DDR2_M.MDQ29: R515.5(B)
DDR2_M.MDQ30: R500.7
DDR2_M.MDQ31: R517.7
DDR2_M.MDQS0: R501.8
DDR2_M.MDQS1: R514.6
DDR2_M.MDQS2: R501.5(B)
DDR2_M.MDQS3: R514.7
DDR2_M.MDQS#0: R501.7
DDR2_M.MDQS#1: R514.5(B)
DDR2_M.MDQS#2: R501.6
DDR2_M.MDQS#3: R514.8
DDR2_M.MODT0: R505.8
DDR2_M.MRAS: R505.6
DDR2_M.MRDQS#0: R513.8
DDR2_M.MRDQS#1: R500.8
DDR2_M.MRDQS#2: R503.7
DDR2_M.MRDQS#3: R516.7
DDR2_M.MS0: R505.7
DDR2_M.MWE: R507.6
VID_D0: X100.3
VID_D1: X100.4
VID_D2: X100.5
VID_D3: X100.6
VID_D4: X100.7
VID_FST: X100.10
VID_QCLK: X100.11
VID_SCL: X100.9
VID_SDA: X100.8
VREF: U504.E2 U505.E2 U506.E2 U507.E2
N00752: U102.2 U104.15
N00770: U102.3 U104.14
N00798: U102.4 U104.13
N00829: U102.5 U104.12
N00863: U102.6 U104.11
N00900: U102.7 U104.10
N01007: U102.8 U104.9
N01138: U102.9 U104.6
N01306: U103.2 U104.5
N01356: U103.3 U104.4
N01440: U103.4 U104.3
N01527: U103.5 U104.2
N01617: U103.6 U104.1
N01710: U103.7 U104.28
N04350: R100.2(B) U100.3 X101.1
N04579: R104.2(B) R108.1 U100.2
N05028: R108.2(B) U100.1 U104.25
N06404: R101.2(B) U100.5 X102.1
N06416: R105.2(B) R109.1 U100.6
N06432: R109.2(B) U100.7 U104.26
N07578: R102.2(B) U100.12 X103.1
N07590: R106.2(B) R110.1 U100.11
N07606: R110.2(B) U100.10 U104.18
N08018: R103.2(B) U100.14 X104.1
N08030: R107.2(B) R111.1 U100.15
N08046: R111.2(B) U100.16 U104.17

Pads without a net: R510 2 3 4 5 6 7; U100 8 9; U101 1 3 5 7 8; U103 11 12; U504 A2 A8 B1 B3 B7 B9 C2 C8 D1 D3 D7 D9 E8 F1 F2 F3 F7 F8 F9 G1 G2 G3 G7 G8 H2 H3 H7 H8 J2 J3 J7 J8 K2 K3 K7 K8 L2 L3 L7 L8; U505 A2 A8 B1 B3 B7 B9 C2 C8 D1 D3 D7 D9 E8 F1 F2 F3 F7 F8 F9 G1 G2 G3 G7 G8 H2 H3 H7 H8 J2 J3 J7 J8 K2 K3 K7 K8 L2 L3 L7 L8; U506 A2 A8 B1 B3 B7 B9 C2 C8 D1 D3 D7 D9 E8 F1 F2 F3 F7 F8 F9 G1 G2 G3 G7 G8 H2 H3 H7 H8 J2 J3 J7 J8 K2 K3 K7 K8 L2 L3 L7 L8; U507 A2 A8 B1 B3 B7 B9 C2 C8 D1 D3 D7 D9 E8 F1 F2 F3 F7 F8 F9 G1 G2 G3 G7 G8 H2 H3 H7 H8 J2 J3 J7 J8 K2 K3 K7 K8 L2 L3 L7 L8

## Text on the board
BOTTOM: 8
TOP: 1 | Demo Design V02/11
GND1: 2
I1: 3
POW1: 4
GND2: 5
I2: 6
POW2: 7
User.11: FIGURE | SIZE | 0.2 | 0.7 | 1.0 | 1.2 | 1.5 | 1.7 | 2.3 | 2.35 | 3.5 | TOLERANCE | +0.1/-0.1 | +0.0/-0.0 | DRILL CHART: TOP to BOTTOM | ALL UNITS ARE IN MILLIMETERS | PLATED | NON-PLATED | QTY | 1267 | 73 | 44 | 6 | 2 | 19 | 3
User.12: FIGURE | SIZE | 0.2 | TOLERANCE | +0.1/-0.1 | DRILL CHART: I1 to I2 | ALL UNITS ARE IN MILLIMETERS | PLATED | QTY | 35
User.13: FIGURE | SIZE | 0.07 | TOLERANCE | +0.1/-0.1 | DRILL CHART: GND1 to I1 | ALL UNITS ARE IN MILLIMETERS | PLATED | QTY | 63
User.14: FIGURE | SIZE | 0.07 | TOLERANCE | +0.1/-0.1 | DRILL CHART: TOP to GND1 | ALL UNITS ARE IN MILLIMETERS | PLATED | QTY | 63
